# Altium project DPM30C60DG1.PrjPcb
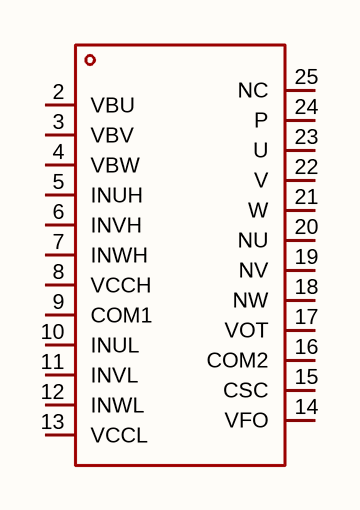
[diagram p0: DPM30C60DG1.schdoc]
1 sheet, 1 parts. Net scope: global (net labels, ports and power ports of the same name join across sheets).

## Sheet DPM30C60DG1.schdoc
size 127 x 101 mm

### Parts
Q?  dpm30c60dg1  [DIP-24_L38.0-W24.0-SPE30S60F-E]  (value not drawn)

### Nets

Not connected (* = marked no-connect by the designer): Q? 2(VBU) 3(VBV) 4(VBW) 5(INUH) 6(INVH) 7(INWH) 8(VCCH) 9(COM1) 10(INUL) 11(INVL) 12(INWL) 13(VCCL) 14(VFO) 15(CSC) 16(COM2) 17(VOT) 18(NW) 19(NV) 20(NU) 21(W) 22(V) 23(U) 24(P) 25(NC)

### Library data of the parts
Q? = dpm30c60dg1: IGBT类型:-;耗散功率(Pd):35W;集射极击穿电压(Vces):600V;集电极电流(Ic):30A;; Manufacturer: CRMICRO(华润微); AddInBom: yes; ModelId: 2a84b5bef10c4f049cb94c89d702080d; ModelTransform: 1496.06,1173.226,0,0,0,0,0,-0.63,-196.85; Pd - Power Dissipation: 35W; Collector-Emitter Breakdown Voltage (Vces): 600V; Current - Collector(Ic): 30A; Current - Collector Pulsed (Icm): 45A; Collector Cut-Off Current (Ices): 1mA; Vce Saturation(VCE(sat)): 1.6V; Reverse Recovery Time(trr): 150ns；60ns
